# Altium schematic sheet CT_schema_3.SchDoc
size 186 x 134 mm
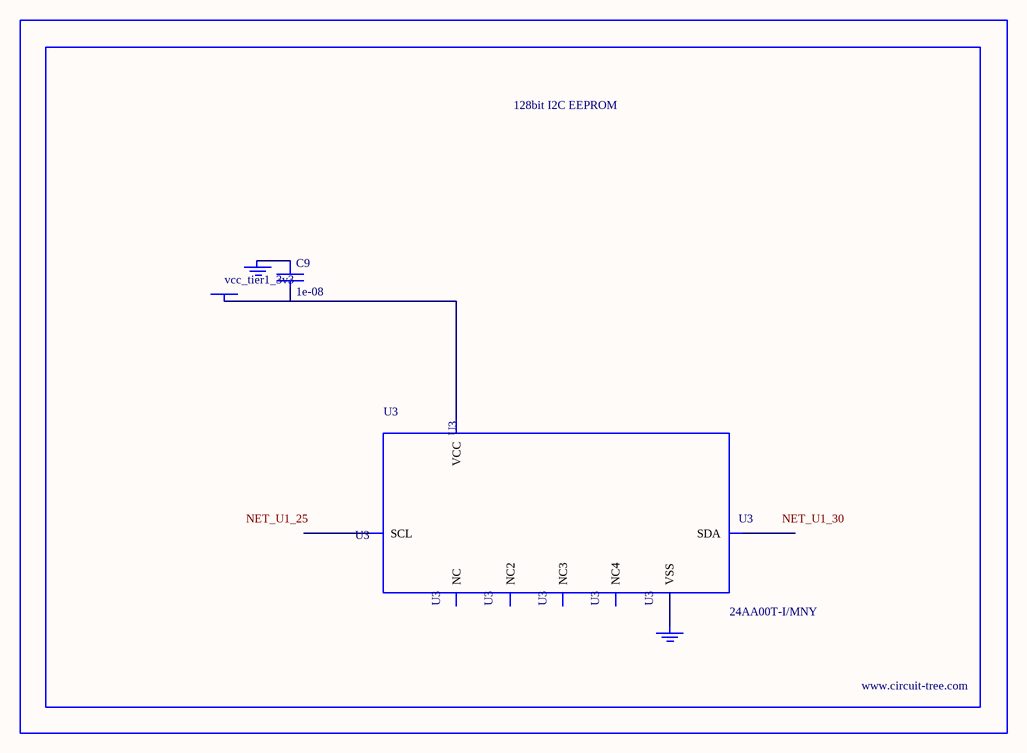
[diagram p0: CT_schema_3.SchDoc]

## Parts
BORDER2  (no value)
C9  1e-08  [C0402]
GND_INSTANCE_2_0  (no value)
GND_INSTANCE_2_1  (no value)
POWER_INSTANCE_2_0  vcc_tier1_3v3
U3  24AA00T-I/MNY  [TDFN-8/6MM]

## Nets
NetC9_1: C9.1 GND_INSTANCE_2_0.0(GND)
NetC9_2: C9.2 POWER_INSTANCE_2_0.0(PWR) U3.8(VCC)
NetGND_INSTANCE_2_1_0: GND_INSTANCE_2_1.0(GND) U3.4(VSS)

Not connected (* = marked no-connect by the designer): U3 1(NC) 2(NC2) 3(NC3) 5(SDA) 6(SCL) 7(NC4)

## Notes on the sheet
- Labels drawn without touching a wire or pin: NET_U1_25, NET_U1_30

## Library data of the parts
BORDER2 = BORDER_PAGE2
C9 = C0402C103K3RAC
GND_INSTANCE_2_0 GND_INSTANCE_2_1 = GND
POWER_INSTANCE_2_0 = PWR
